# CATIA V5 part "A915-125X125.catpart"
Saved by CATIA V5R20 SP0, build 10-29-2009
Part number: A915-125X125
Source: Unknown
Property "A": "75.000"
Property "ARTICLENO": "A915-125X125"
Property "BOMINFO": "A915-125X125"
Property "CODE": "A915-125X125"
Property "CREATOR": "CADENAS GmbH"
Property "D": "13.500"
Property "D1": "20.000"
Property "FORM": "C"
Property "L": "125.000"
Property "L1": "25.000"
Property "L2": "75.000"
Property "LINA": "A915-125X125"
Property "NB": "A915-125X125"
Property "NBSYN": "$CODE."
Property "NN": "A915"
Property "NT": "VDI 3357 Wear Plates, steel"
Property "SCREW": "M12x25"
Property "SUPPLIER": "CF"
Property "T": "13.000"
Property "W": "125.000"
Bounding box of the stored display mesh (mm): x 0 to 20, y 0 to 125, z -62.5 to 62.5
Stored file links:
  C:\Users\borellobunino\Desktop\3D X SITO CF\A915\GSB_OILLESS_G22501125125\CATIAV5\A915-125X125.catpart
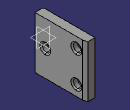
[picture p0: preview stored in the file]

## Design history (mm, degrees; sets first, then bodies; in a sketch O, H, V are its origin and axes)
Body1 "Geometry.1" (main body)
  Solid1 "A915-125X125.catpart": solid without history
